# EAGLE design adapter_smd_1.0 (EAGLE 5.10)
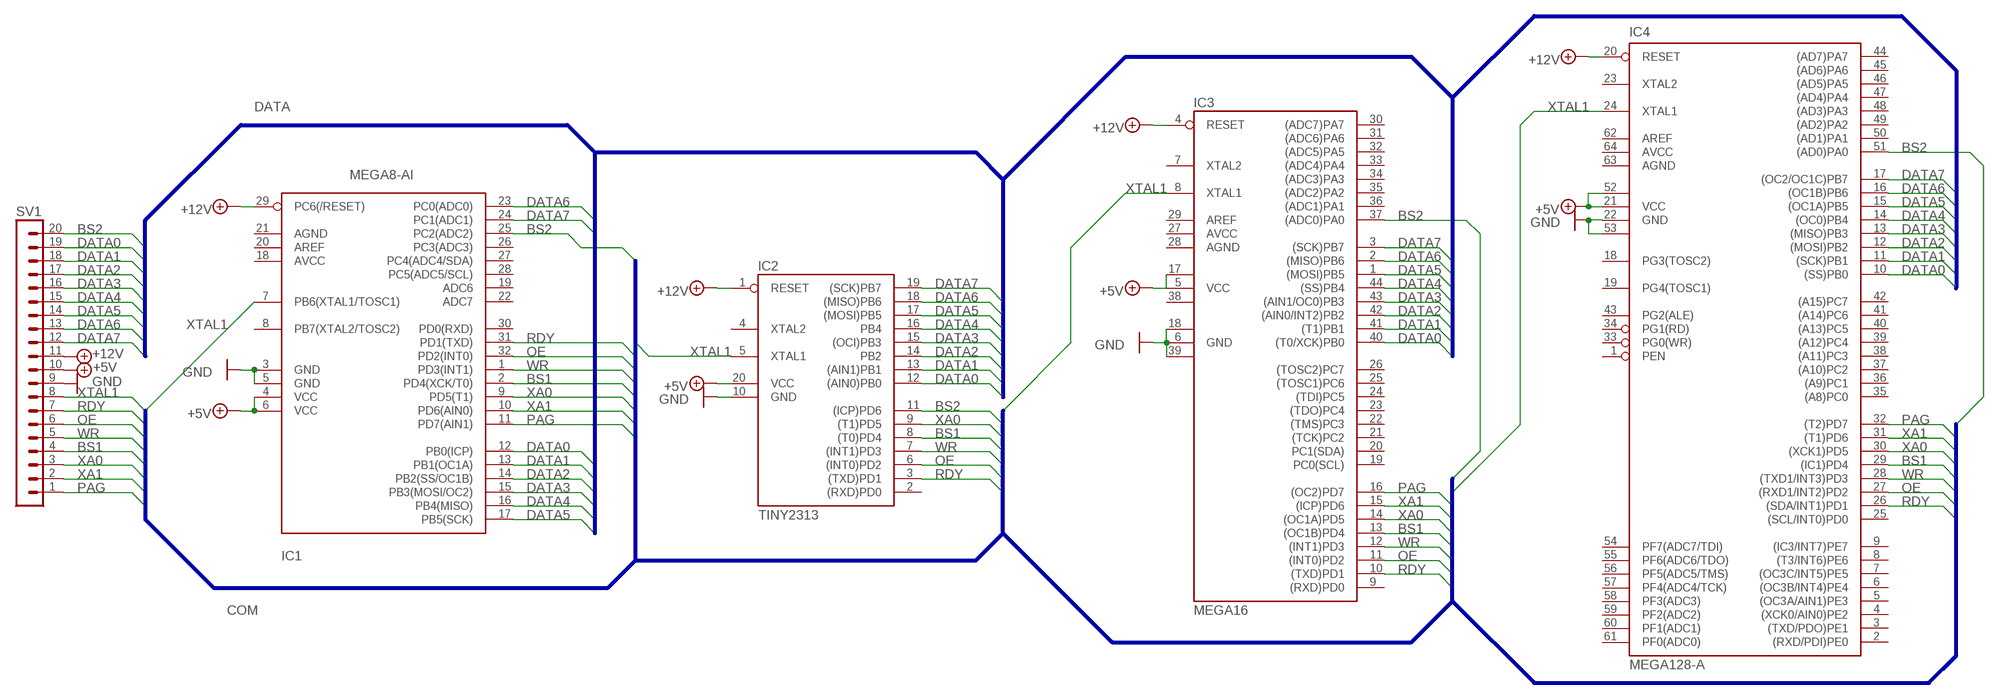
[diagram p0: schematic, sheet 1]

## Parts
IC1  MEGA8-AI  [TQFP32-08]
IC2  TINY2313  AT90S2313S  [SO20L]
IC3  MEGA16  MEGA16-A  [TQFP44]
IC4  MEGA128-A  [TQFP64]
SV1  MA20-1  [MA20-1]

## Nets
+5V: IC1.4(VCC) IC1.6(VCC) IC2.20(VCC) IC3.5(VCC) IC3.17(VCC1) IC4.21(VCC) IC4.52(VCC1) SV1.10
+12V: IC1.29(PC6(/RESET)) IC2.1(RESET) IC3.4(RESET) IC4.20(RESET) SV1.11
BS1: IC1.2(PD4(XCK/T0)) IC2.8((T0)PD4) IC3.13((OC1B)PD4) IC4.29((IC1)PD4) SV1.4
BS2: IC1.25(PC2(ADC2)) IC2.11((ICP)PD6) IC3.37((ADC0)PA0) IC4.51((AD0)PA0) SV1.20
DATA0: IC1.12(PB0(ICP)) IC2.12((AIN0)PB0) IC3.40((T0/XCK)PB0) IC4.10((SS)PB0) SV1.19
DATA1: IC1.13(PB1(OC1A)) IC2.13((AIN1)PB1) IC3.41((T1)PB1) IC4.11((SCK)PB1) SV1.18
DATA2: IC1.14(PB2(SS/OC1B)) IC2.14(PB2) IC3.42((AIN0/INT2)PB2) IC4.12((MOSI)PB2) SV1.17
DATA3: IC1.15(PB3(MOSI/OC2)) IC2.15((OCI)PB3) IC3.43((AIN1/OC0)PB3) IC4.13((MISO)PB3) SV1.16
DATA4: IC1.16(PB4(MISO)) IC2.16(PB4) IC3.44((SS)PB4) IC4.14((OC0)PB4) SV1.15
DATA5: IC1.17(PB5(SCK)) IC2.17((MOSI)PB5) IC3.1((MOSI)PB5) IC4.15((OC1A)PB5) SV1.14
DATA6: IC1.23(PC0(ADC0)) IC2.18((MISO)PB6) IC3.2((MISO)PB6) IC4.16((OC1B)PB6) SV1.13
DATA7: IC1.24(PC1(ADC1)) IC2.19((SCK)PB7) IC3.3((SCK)PB7) IC4.17((OC2/OC1C)PB7) SV1.12
GND: IC1.3(GND) IC1.5(GND) IC2.10(GND) IC3.6(GND) IC3.18(GND1) IC3.39(GND2) IC4.22(GND) IC4.53(GND1) SV1.9
OE: IC1.32(PD2(INT0)) IC2.6((INT0)PD2) IC3.11((INT0)PD2) IC4.27((RXD1/INT2)PD2) SV1.6
PAG: IC1.11(PD7(AIN1)) IC3.16((OC2)PD7) IC4.32((T2)PD7) SV1.1
RDY: IC1.31(PD1(TXD)) IC2.3((TXD)PD1) IC3.10((TXD)PD1) IC4.26((SDA/INT1)PD1) SV1.7
WR: IC1.1(PD3(INT1)) IC2.7((INT1)PD3) IC3.12((INT1)PD3) IC4.28((TXD1/INT3)PD3) SV1.5
XA0: IC1.9(PD5(T1)) IC2.9((T1)PD5) IC3.14((OC1A)PD5) IC4.30((XCK1)PD5) SV1.3
XA1: IC1.10(PD6(AIN0)) IC3.15((ICP)PD6) IC4.31((T1)PD6) SV1.2
XTAL1: IC1.7(PB6(XTAL1/TOSC1)) IC2.5(XTAL1) IC3.8(XTAL1) IC4.24(XTAL1) SV1.8
Unconnected: IC1.8(PB7(XTAL2/TOSC2)) IC1.18(AVCC) IC1.19(ADC6) IC1.20(AREF) IC1.21(AGND) IC1.22(ADC7) IC1.26(PC3(ADC3)) IC1.27(PC4(ADC4/SDA)) IC1.28(PC5(ADC5/SCL)) IC1.30(PD0(RXD)) IC2.2((RXD)PD0) IC2.4(XTAL2) IC3.7(XTAL2) IC3.9((RXD)PD0) IC3.19(PC0(SCL)) IC3.20(PC1(SDA)) IC3.21((TCK)PC2) IC3.22((TMS)PC3) IC3.23((TDO)PC4) IC3.24((TDI)PC5) IC3.25((TOSC1)PC6) IC3.26((TOSC2)PC7) IC3.30((ADC7)PA7) IC3.31((ADC6)PA6) IC3.32((ADC5)PA5) IC3.33((ADC4)PA4) IC3.34((ADC3)PA3) IC3.35((ADC2)PA2) IC3.36((ADC1)PA1) IC4.1(PEN) IC4.2((RXD/PDI)PE0) IC4.3((TXD/PDO)PE1) IC4.4((XCK0/AIN0)PE2) IC4.5((OC3A/AIN1)PE3) IC4.6((OC3B/INT4)PE4) IC4.7((OC3C/INT5)PE5) IC4.8((T3/INT6)PE6) IC4.9((IC3/INT7)PE7) IC4.18(PG3(TOSC2)) IC4.19(PG4(TOSC1)) IC4.23(XTAL2) IC4.25((SCL/INT0)PD0) IC4.33(PG0(WR)) IC4.34(PG1(RD)) IC4.35((A8)PC0) IC4.36((A9)PC1) IC4.37((A10)PC2) IC4.38((A11)PC3) IC4.39((A12)PC4) IC4.40((A13)PC5) IC4.41((A14)PC6) IC4.42((A15)PC7) IC4.43(PG2(ALE)) IC4.44((AD7)PA7) IC4.45((AD6)PA6) IC4.46((AD5)PA5) IC4.47((AD4)PA4) IC4.48((AD3)PA3) IC4.49((AD2)PA2) IC4.50((AD1)PA1) IC4.54(PF7(ADC7/TDI)) IC4.55(PF6(ADC6/TDO)) IC4.56(PF5(ADC5/TMS)) IC4.57(PF4(ADC4/TCK)) IC4.58(PF3(ADC3)) IC4.59(PF2(ADC2)) IC4.60(PF1(ADC1)) IC4.61(PF0(ADC0)) IC4.62(AREF) IC4.63(AGND) IC4.64(AVCC)

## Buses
DATA
COM

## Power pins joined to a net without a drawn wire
AGND: IC3.28(AGND)
AREF: IC3.29(AREF)
AVCC: IC3.27(AVCC)
VCC2: IC3.38(VCC2)

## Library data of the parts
IC1 = avr-6:MEGA8: MICROCONTROLLER 8 Kbytes FLASH 1 kbytes SRAM 512 bytes EEPROM USART 6-channel 10 bit ADC 2-channel 8 bit ADC
IC2 = atmel:AT90S2313: MICROCONTROLLER 2 Kbytes FLASH 128 bytes SRAM 128 bytes EEPROM UART
IC3 = avr-6:MEGA16: MICROCONTROLLER 16 Kbytes FLASH 1 kbytes SRAM 512 bytes EEPROM USART 8-channel 10 bit ADC
IC4 = avr-6:MEGA128: MICROCONTROLLER 128 Kbytes FLASH 4 Kbytes SRAM 4 Kbytes EEPROM DUAL USART 8-channel 10 bit ADC
SV1 = con-lstb:MA20-1: PIN HEADER

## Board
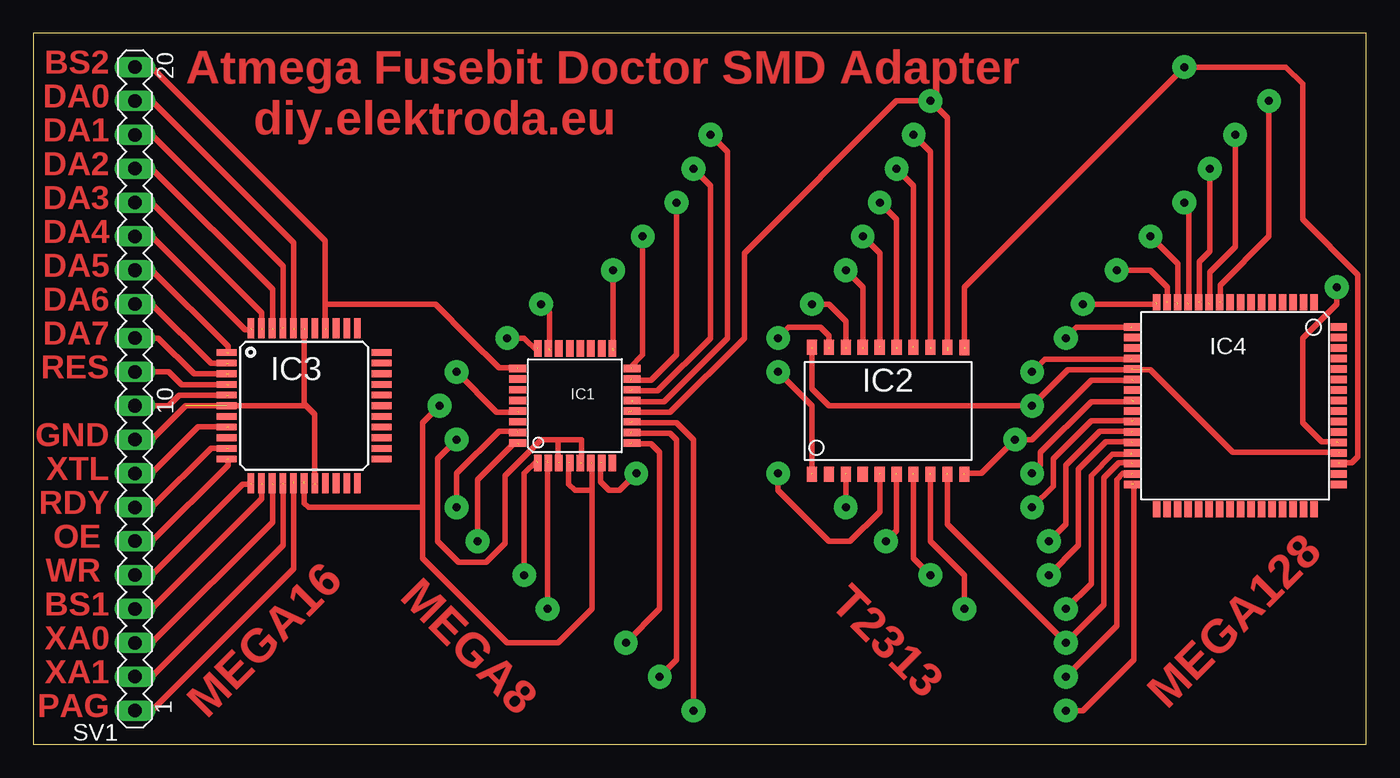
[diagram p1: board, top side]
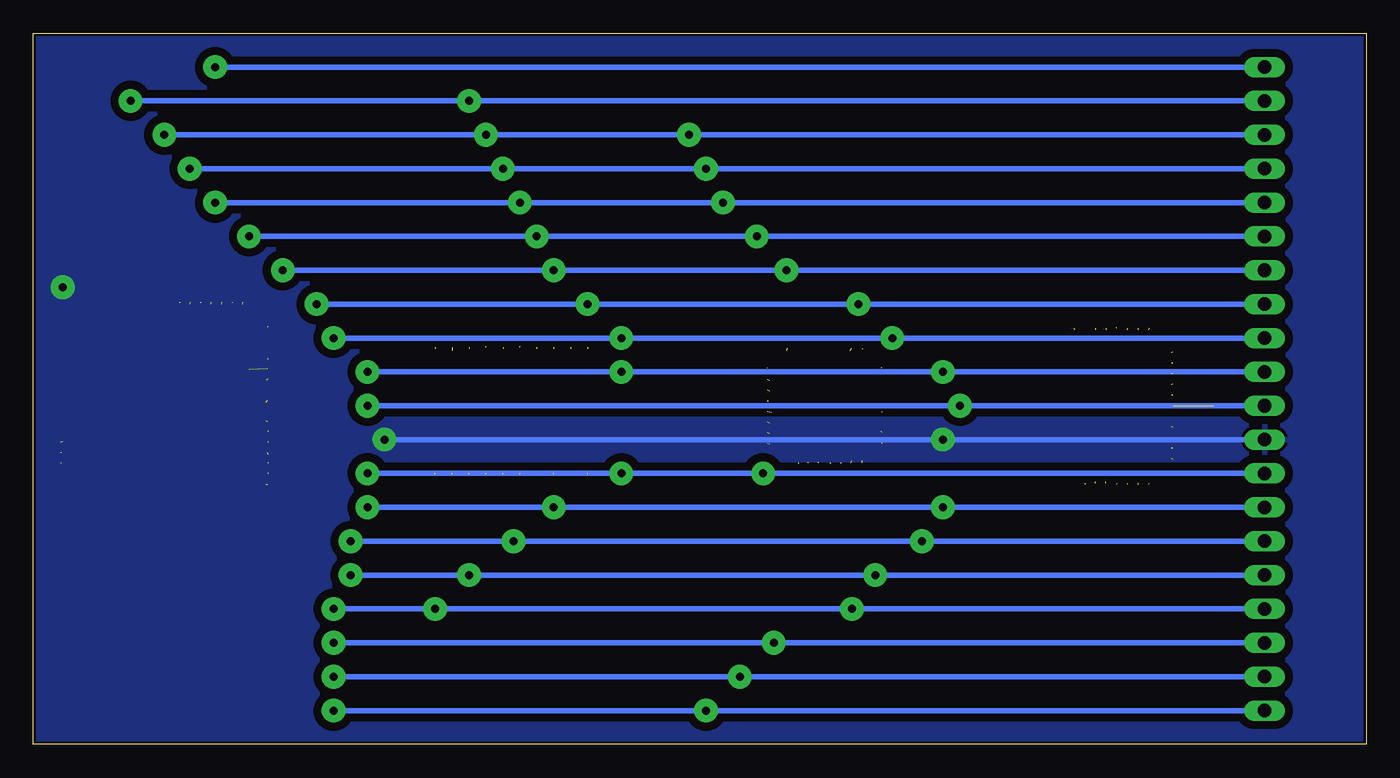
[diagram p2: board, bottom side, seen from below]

Size 100 x 53.33 mm. Coordinates in mm from the lower left corner, seen from the top.
Outline: 0,0 100,0 100,53.33 0,53.33 0,0
Copper layers (1*16): Top 0.035mm / dielectric 1.5mm / Bottom 0.035mm
Design rules "default *": minimum track width 10mil, minimum drill 24mil, track to track 24mil, track to pad 24mil, pad to pad 8mil, via to via 8mil, smd to smd 8mil, copper to edge 8mil, drill to drill 8mil, minimum pad ring 10mil, minimum via ring 8mil, stop-mask expansion 4mil, vias tented up to drill 0mil, thermal gap 10mil

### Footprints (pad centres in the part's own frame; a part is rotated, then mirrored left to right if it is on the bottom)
TQFP32-08 = smd 1.27 x 0.559: 1 -4.293,2.8; 2 -4.293,2; 3 -4.293,1.2; 4 -4.293,0.4; 5 -4.293,-0.4; 6 -4.293,-1.2; 7 -4.293,-2; 8 -4.293,-2.8; 17 4.293,-2.8; 18 4.293,-2; 19 4.293,-1.2; 20 4.293,-0.4; 21 4.293,0.4; 22 4.293,1.2; 23 4.293,2; 24 4.293,2.8 | smd 0.559 x 1.27: 9 -2.8,-4.293; 10 -2,-4.293; 11 -1.2,-4.293; 12 -0.4,-4.293; 13 0.4,-4.293; 14 1.2,-4.293; 15 2,-4.293; 16 2.8,-4.293; 25 2.8,4.293; 26 2,4.293; 27 1.2,4.293; 28 0.4,4.293; 29 -0.4,4.293; 30 -1.2,4.293; 31 -2,4.293; 32 -2.8,4.293
SO20L = smd 0.762 x 1.143: 1 -5.08,-5.131; 2 -3.81,-5.131; 3 -2.54,-5.131; 4 -1.27,-5.131; 5 0,-5.131; 6 1.27,-5.131; 7 2.54,-5.131; 8 3.81,-5.131; 9 5.08,-5.131; 10 6.35,-5.131; 11 6.35,4.369; 12 5.08,4.394; 13 3.81,4.394; 14 2.54,4.394; 15 1.27,4.394; 16 0,4.394; 17 -1.27,4.394; 18 -2.54,4.394; 19 -3.81,4.394; 20 -5.08,4.394
TQFP44 = smd 1.5 x 0.5: 1 -5.8,4; 2 -5.8,3.2; 3 -5.8,2.4; 4 -5.8,1.6; 5 -5.8,0.8; 6 -5.8,0; 7 -5.8,-0.8; 8 -5.8,-1.6; 9 -5.8,-2.4; 10 -5.8,-3.2; 11 -5.8,-4; 23 5.8,-4; 24 5.8,-3.2; 25 5.8,-2.4; 26 5.8,-1.6; 27 5.8,-0.8; 28 5.8,0; 29 5.8,0.8; 30 5.8,1.6; 31 5.8,2.4; 32 5.8,3.2; 33 5.8,4 | smd 0.5 x 1.5: 12 -4,-5.8; 13 -3.2,-5.8; 14 -2.4,-5.8; 15 -1.6,-5.8; 16 -0.8,-5.8; 17 0,-5.8; 18 0.8,-5.8; 19 1.6,-5.8; 20 2.4,-5.8; 21 3.2,-5.8; 22 4,-5.8; 34 4,5.8; 35 3.2,5.8; 36 2.4,5.8; 37 1.6,5.8; 38 0.8,5.8; 39 0,5.8; 40 -0.8,5.8; 41 -1.6,5.8; 42 -2.4,5.8; 43 -3.2,5.8; 44 -4,5.8
TQFP64 = smd 1.194 x 0.559: 1 -7.76,5.905; 2 -7.76,5.118; 3 -7.76,4.331; 4 -7.76,3.543; 5 -7.76,2.756; 6 -7.76,1.968; 7 -7.76,1.181; 8 -7.76,0.394; 9 -7.76,-0.394; 10 -7.76,-1.181; 11 -7.76,-1.968; 12 -7.76,-2.756; 13 -7.76,-3.543; 14 -7.76,-4.331; 15 -7.76,-5.118; 16 -7.76,-5.905; 33 7.76,-5.905; 34 7.76,-5.118; 35 7.76,-4.331; 36 7.76,-3.543; 37 7.76,-2.756; 38 7.76,-1.968; 39 7.76,-1.181; 40 7.76,-0.394; 41 7.76,0.394; 42 7.76,1.181; 43 7.76,1.968; 44 7.76,2.756; 45 7.76,3.543; 46 7.76,4.331; 47 7.76,5.118; 48 7.76,5.905 | smd 0.559 x 1.194: 17 -5.905,-7.76; 18 -5.118,-7.76; 19 -4.331,-7.76; 20 -3.543,-7.76; 21 -2.756,-7.76; 22 -1.968,-7.76; 23 -1.181,-7.76; 24 -0.394,-7.76; 25 0.394,-7.76; 26 1.181,-7.76; 27 1.968,-7.76; 28 2.756,-7.76; 29 3.543,-7.76; 30 4.331,-7.76; 31 5.118,-7.76; 32 5.905,-7.76; 49 5.905,7.76; 50 5.118,7.76; 51 4.331,7.76; 52 3.543,7.76; 53 2.756,7.76; 54 1.968,7.76; 55 1.181,7.76; 56 0.394,7.76; 57 -0.394,7.76; 58 -1.181,7.76; 59 -1.968,7.76; 60 -2.756,7.76; 61 -3.543,7.76; 62 -4.331,7.76; 63 -5.118,7.76; 64 -5.905,7.76
MA20-1 = drill 1.016 long: 1 -24.13,0; 2 -21.59,0; 3 -19.05,0; 4 -16.51,0; 5 -13.97,0; 6 -11.43,0; 7 -8.89,0; 8 -6.35,0; 9 -3.81,0; 10 -1.27,0; 11 1.27,0; 12 3.81,0; 13 6.35,0; 14 8.89,0; 15 11.43,0; 16 13.97,0; 17 16.51,0; 18 19.05,0; 19 21.59,0; 20 24.13,0

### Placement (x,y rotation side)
IC1  40.64,25.4 90 top
IC2  63.5,25.4 0 top
IC3  20.32,25.4 0 top
IC4  90.17,25.4 270 top
SV1  7.62,26.67 90 top

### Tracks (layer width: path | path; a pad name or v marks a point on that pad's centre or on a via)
+5V  (via drill 0.6 pad 1.78)  (7 unrouted)
  Top 0.406: SV1.10 10.16,25.4 10.95,26.19 14.61,26.19 | 58.42,29.69 58.42,26.67 59.69,25.4 v74.93,25.4 77.63,28.1 83.82,28.1 90.01,21.91 97.95,21.91 | v30.48,25.4 29.21,24.13 29.21,17.78 | 29.21,17.78 29.21,13.97 35.56,7.62 39.37,7.62 41.91,10.16 41.91,19.05 | 41.91,19.05 41.91,21.11 | 29.21,17.78 20.64,17.78 20.32,18.1 20.32,19.68 | 41.91,19.05 40.64,19.05 40.16,19.53 40.16,21.11
  Bottom 0.406: SV1.10 v30.48,25.4 v74.93,25.4
+12V  (via drill 0.6 pad 1.78)  (4 unrouted)
  Top 0.406: v74.93,27.94 75.88,28.89 82.39,28.89 | SV1.11 10.16,27.94 11.11,26.99 14.61,26.99 | v55.88,27.94 58.42,25.4 58.42,20.32 | v31.75,27.94 34.77,24.92 36.35,24.92
  Bottom 0.406: SV1.11 v31.75,27.94 v55.88,27.94 v74.93,27.94
BS1  (via drill 0.6 pad 1.78)  (4 unrouted)
  Top 0.406: v77.47,10.16 79.38,12.06 79.38,20.16 80.96,21.75 82.39,21.75 | SV1.4 8.89,10.16 17.14,18.41 17.14,19.53 | v69.85,10.16 69.85,12.7 67.31,15.24 67.31,20.32 | v38.58,10.16 38.58,10.48 38.58,15.56 38.58,16.99 38.58,21.27
  Bottom 0.406: SV1.4 v38.58,10.16 v69.85,10.16 v77.47,10.16
BS2  (via drill 0.6 pad 1.78)  (4 unrouted)
  Top 0.406: 97.95,21.11 98.9,21.11 99.38,21.59 99.38,35.24 95.25,39.37 95.25,49.53 93.98,50.8 v86.36,50.8 69.85,34.29 69.85,29.69 | SV1.20 8.89,50.8 21.91,37.78 21.91,33.02 | 21.91,31.11 21.91,33.02 | 21.91,33.02 30.16,33.02 32.7,30.48 | 32.7,30.48 | 32.7,30.48 34.92,28.26 36.35,28.26
  Bottom 0.406: SV1.20 v86.36,50.8
DATA0  (via drill 0.6 pad 1.78)  (4 unrouted)
  Top 0.406: v92.71,48.26 92.71,38.1 89.06,34.45 89.06,33.18 | SV1.19 8.89,48.26 19.53,37.62 19.53,31.11 | 68.58,29.53 68.58,46.99 v67.31,48.26 64.77,48.26 53.34,36.83 53.34,30.48 47.78,24.92 44.61,24.92
  Bottom 0.406: SV1.19 v67.31,48.26 v92.71,48.26
DATA1  (via drill 0.6 pad 1.78)  (4 unrouted)
  Top 0.406: v90.17,45.72 90.17,37.31 88.27,35.4 88.27,33.02 | SV1.18 8.89,45.72 18.73,35.88 18.73,31.27 | v66.04,45.72 67.31,44.45 67.31,29.69 | v50.8,45.72 52.07,44.45 52.07,30.48 47.31,25.72 44.93,25.72
  Bottom 0.406: SV1.18 v50.8,45.72 v66.04,45.72 v90.17,45.72
DATA2  (via drill 0.6 pad 1.78)  (4 unrouted)
  Top 0.406: v88.27,43.18 88.27,36.99 87.47,36.2 87.47,33.18 | SV1.17 8.89,43.18 17.94,34.13 17.94,31.11 | v64.77,43.18 66.04,41.91 66.04,29.84 | v49.53,43.18 50.8,41.91 50.8,30.48 46.83,26.51 44.77,26.51
  Bottom 0.406: SV1.17 v49.53,43.18 v64.77,43.18 v88.27,43.18
DATA3  (via drill 0.6 pad 1.78)  (4 unrouted)
  Top 0.406: v86.36,40.64 86.68,40.32 86.68,33.02 | SV1.16 8.89,40.64 17.14,32.38 17.14,31.11 | v63.5,40.64 64.77,39.37 64.77,29.69 | v48.26,40.64 48.26,29.21 46.35,27.3 44.77,27.3
  Bottom 0.406: SV1.16 v48.26,40.64 v63.5,40.64 v86.36,40.64
DATA4  (via drill 0.6 pad 1.78)  (4 unrouted)
  Top 0.406: v83.82,38.1 85.88,36.04 85.88,33.02 | SV1.15 8.89,38.1 15.88,31.11 16.35,31.11 | v62.23,38.1 63.5,36.83 63.5,29.84 | v45.72,38.1 45.72,29.21 44.77,28.26 44.93,28.26
  Bottom 0.406: SV1.15 v45.72,38.1 v62.23,38.1 v83.82,38.1
DATA5  (via drill 0.6 pad 1.78)  (4 unrouted)
  Top 0.406: v81.28,35.56 83.82,35.56 85.09,34.29 85.09,33.18 | SV1.14 8.89,35.56 14.61,29.84 14.61,29.37 | v60.96,35.56 62.23,34.29 62.23,29.69 | v43.5,35.56 43.5,29.53
  Bottom 0.406: SV1.14 v43.5,35.56 v60.96,35.56 v81.28,35.56
DATA6  (via drill 0.6 pad 1.78)  (4 unrouted)
  Top 0.406: v78.74,33.02 84.3,33.02 | SV1.13 8.89,33.02 13.34,28.57 14.61,28.57 | v58.42,33.02 59.69,33.02 60.96,31.75 60.96,29.69 | v38.1,33.02 38.73,32.38 38.73,29.53
  Bottom 0.406: SV1.13 v38.1,33.02 v58.42,33.02 v78.74,33.02
DATA7  (via drill 0.6 pad 1.78)  (4 unrouted)
  Top 0.406: v77.47,30.48 78.26,31.27 82.39,31.27 | SV1.12 9.37,30.48 12.06,27.78 14.61,27.78 | v55.88,30.48 56.67,31.27 59.05,31.27 59.69,30.64 59.69,29.69 | v35.56,30.48 36.83,30.48 37.78,29.53 37.78,29.69
  Bottom 0.406: SV1.12 v35.56,30.48 v55.88,30.48 v77.47,30.48
GND  (via drill 0.6 pad 1.78)  (8 unrouted)
  Top 0.406: 82.55,27.3 79.38,27.3 74.93,22.86 v73.66,22.86 71.12,20.32 69.85,20.32 | SV1.9 8.89,22.86 11.43,25.4 20.32,25.4 20.32,25.56 | v31.75,22.86 30.32,21.43 30.32,15.24 31.91,13.65 33.97,13.65 35.4,15.08 35.4,20.16 38.1,22.86 39.37,22.86 | 39.37,22.86 39.37,21.11 | v97.79,34.29 97.79,33.02 95.25,30.48 95.25,24.13 96.68,22.7 97.79,22.7 | 20.32,25.56 20.32,31.11 | 20.32,25.56 21.11,24.77 21.11,19.53 | 39.37,22.86 41.12,22.86 41.12,21.11
  Bottom 0.406: SV1.9 v31.75,22.86 v73.66,22.86
  pour Bottom: 0,53.34 100.33,53.34 100.33,0 0,0
OE  (via drill 0.6 pad 1.78)  (4 unrouted)
  Top 0.406: v76.2,15.24 77.47,16.51 77.47,20.95 80.01,23.5 82.39,23.5 | SV1.6 8.89,15.24 14.61,20.95 14.61,21.43 | v63.98,15.24 64.77,16.03 64.77,20.32 | v33.34,15.24 33.34,19.84 36.04,22.54 36.35,22.54
  Bottom 0.406: SV1.6 v33.34,15.24 v63.98,15.24 v76.2,15.24
PAG  (via drill 0.6 pad 1.78)  (3 unrouted)
  Top 0.406: v77.47,2.54 78.74,2.54 82.55,6.35 82.55,19.53 | SV1.1 8.89,2.54 19.53,13.18 19.53,19.68 | v49.53,2.54 49.53,22.86 48.26,24.13 44.77,24.13
  Bottom 0.406: SV1.1 v49.53,2.54 v77.47,2.54
RDY  (via drill 0.6 pad 1.78)  (4 unrouted)
  Top 0.406: v74.93,17.78 76.52,19.37 76.52,21.43 79.38,24.29 82.55,24.29 | SV1.7 8.89,17.78 13.34,22.23 14.61,22.23 | v60.96,17.78 60.96,20.32 | v31.75,17.78 31.75,20.32 34.92,23.5 36.35,23.5
  Bottom 0.406: SV1.7 v31.75,17.78 v60.96,17.78 v74.93,17.78
WR  (via drill 0.6 pad 1.78)  (4 unrouted)
  Top 0.406: v76.2,12.7 78.42,14.92 78.42,20.64 80.49,22.7 82.39,22.7 | SV1.5 8.89,12.7 15.72,19.53 16.35,19.53 | v67.31,12.7 66.04,13.97 66.04,20.32 | v36.83,12.7 36.83,20.32 37.78,21.27
  Bottom 0.406: SV1.5 v36.83,12.7 v67.31,12.7 v76.2,12.7
XA0  (via drill 0.6 pad 1.78)  (4 unrouted)
  Top 0.406: 82.39,21.11 81.44,21.11 80.33,20 80.33,10.48 v77.47,7.62 68.58,16.51 68.58,20.32 | SV1.3 8.89,7.62 17.94,16.67 17.94,19.53 | v44.45,7.62 46.99,10.16 46.99,19.05 46.99,21.91 46.35,22.54 44.77,22.54
  Bottom 0.406: SV1.3 v44.45,7.62 v77.47,7.62
XA1  (via drill 0.6 pad 1.78)  (3 unrouted)
  Top 0.406: v77.47,5.08 81.28,8.89 81.28,19.84 81.76,20.32 82.39,20.32 | SV1.2 8.89,5.08 18.73,14.92 18.73,19.53 | v46.99,5.08 48.26,6.35 48.26,22.86 47.78,23.34 44.77,23.34
  Bottom 0.406: SV1.2 v46.99,5.08 v77.47,5.08
XTAL1  (via drill 0.6 pad 1.78)  (4 unrouted)
  Top 0.406: v74.93,20.32 75.56,20.95 75.56,21.91 79.38,25.72 82.55,25.72 | SV1.8 8.89,20.32 12.38,23.81 14.61,23.81 | v55.88,20.32 55.88,19.05 59.69,15.24 61.28,15.24 63.5,17.46 63.5,20.32 | v45.24,20.32 43.97,19.05 43.18,19.05 42.55,19.68 42.55,21.11
  Bottom 0.406: SV1.8 v45.24,20.32 v55.88,20.32 v74.93,20.32

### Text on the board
Top: BS2 | DA0 | Atmega Fusebit Doctor SMD Adapter | DA1 | diy.elektroda.eu | DA2 | DA3 | DA4 | DA5 | DA6 | DA7 | RES | GND | XTL | RDY | OE | WR | MEGA16 | BS1 | XA0 | XA1 | T2313 | PAG | MEGA8 | MEGA128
